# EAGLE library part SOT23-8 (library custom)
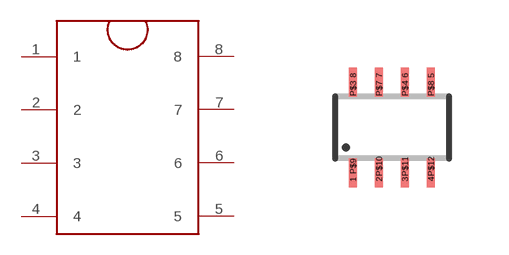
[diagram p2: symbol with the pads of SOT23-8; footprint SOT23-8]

Designator prefix -

## SOT23-8  [SOT23-8]
1  1
2  2
3  3
4  4
5  5
6  6
7  7
8  8

## Footprint SOT23-8 (pad centres in mm)
Small Outline Transistor 8 lead
smd 0.203 x 0.406: 1 -0.975,-1.3; 2 -0.325,-1.3; 3 0.325,-1.3; 4 0.975,-1.3; 5 0.975,1.3; 6 0.325,1.3; 7 -0.325,1.3; 8 -0.975,1.3; P$3 -0.975,0.975; P$4 0.325,0.975; P$7 -0.325,0.975; P$8 0.975,0.975; P$9 -0.975,-0.975; P$10 -0.325,-0.975; P$11 0.325,-0.975; P$12 0.975,-0.975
